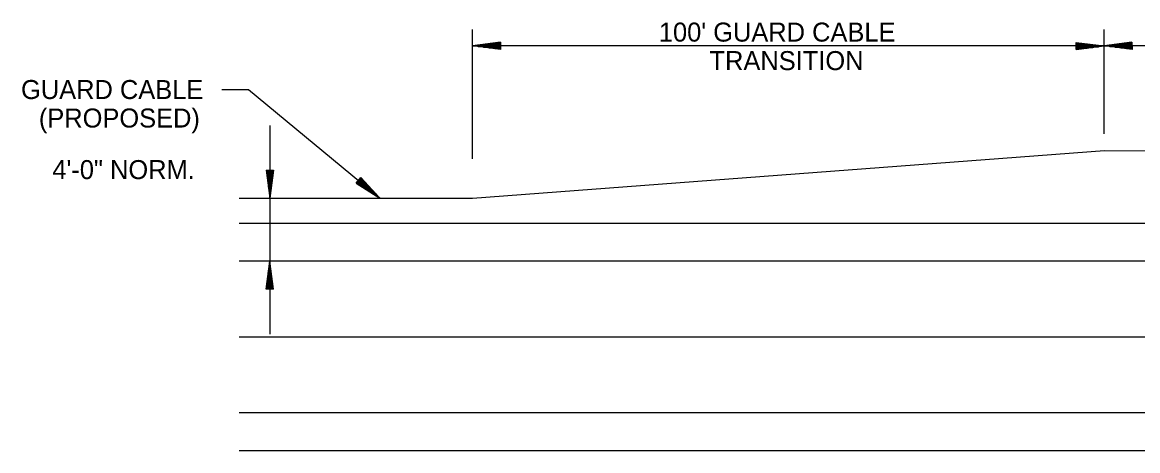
# Model space of a CAD drawing. Extents: x -2842 to 2681, y -2139 to 474.
# Drawn here: x -2842.2 to -2490.2, y -1672.7 to -1537.5 of the extents above; entities that cross this region are included whole.
import ezdxf

# ---------------------------------------------------------------- set-up
doc = ezdxf.new("R2010")
doc.units = 0
for name, color, linetype in [('Default', 7, 'Continuous'), ('R_Border', 7, 'Continuous'), ('R_Border Notes', 7, 'Continuous'), ('R_Grid', 7, 'Continuous')]:
    doc.layers.add(name, color=color, linetype=linetype)

msp = doc.modelspace()

# ---------------------------------------------------------------- linework, layer by layer
at = {"layer": 'Default'}
for p, q in [((-2700.16, -1593), (-2500.66, -1577.94)), ((-2773.74, -1593), (-2700.16, -1593)), ((-2381.26, -1600.97), (-2773.74, -1600.97)), ((-1662.85, -1612.93), (-2773.74, -1612.93)), ((-1661.2, -1660.76), (-2773.74, -1660.76)), ((-1815.02, -1672.72), (-2773.74, -1672.72))]:
    msp.add_line(p, q, dxfattribs=at)
msp.add_lwpolyline([(-2500.66, -1577.94), (-2380.62, -1578.11), (-2266.04, -1580.67)], dxfattribs=at)
at = {"layer": 'R_Border Notes'}
for p, q in [((-2700.16, -1580.53), (-2700.16, -1539.7)), ((-2500.85, -1572.68), (-2500.85, -1539.7)), ((-2691.34, -1543.8), (-2700.16, -1544.95)), ((-2500.85, -1544.95), (-2700.16, -1544.95)), ((-2700.16, -1544.95), (-2691.33, -1544.95)), ((-2691.33, -1546.09), (-2700.16, -1544.95)), ((-2691.34, -1544.72), (-2698.37, -1544.72)), ((-2691.33, -1544.49), (-2696.64, -1544.5)), ((-2691.34, -1544.26), (-2694.86, -1544.26)), ((-2691.33, -1544.03), (-2693.07, -1544.04)), ((-2691.34, -1543.8), (-2691.33, -1546.09)), ((-2509.68, -1544.27), (-2506.15, -1544.26)), ((-2509.68, -1544.49), (-2504.37, -1544.5)), ((-2509.67, -1543.81), (-2500.85, -1544.95)), ((-2509.67, -1546.1), (-2509.67, -1543.81)), ((-2509.67, -1544.03), (-2507.94, -1544.03)), ((-2509.67, -1544.73), (-2502.64, -1544.73)), ((-2500.85, -1544.95), (-2509.67, -1544.95)), ((-2509.67, -1546.1), (-2500.85, -1544.95)), ((-2492.03, -1543.8), (-2500.85, -1544.95)), ((-2363.24, -1544.95), (-2500.85, -1544.95)), ((-2500.85, -1544.95), (-2492.02, -1544.95)), ((-2492.02, -1546.09), (-2500.85, -1544.95)), ((-2492.03, -1544.72), (-2499.06, -1544.72)), ((-2492.02, -1544.49), (-2497.33, -1544.5)), ((-2492.03, -1544.26), (-2495.55, -1544.26)), ((-2492.02, -1544.03), (-2493.76, -1544.04)), ((-2492.03, -1543.8), (-2492.02, -1546.09)), ((-2691.33, -1545.17), (-2698.37, -1545.18)), ((-2691.33, -1545.41), (-2696.63, -1545.41)), ((-2691.33, -1545.63), (-2694.85, -1545.64)), ((-2691.33, -1545.87), (-2693.06, -1545.87)), ((-2509.67, -1545.18), (-2502.64, -1545.18)), ((-2509.67, -1545.41), (-2504.37, -1545.4)), ((-2509.67, -1545.64), (-2506.15, -1545.64)), ((-2509.67, -1545.87), (-2507.94, -1545.86)), ((-2492.02, -1545.17), (-2499.06, -1545.18)), ((-2492.02, -1545.41), (-2497.32, -1545.41)), ((-2492.02, -1545.63), (-2495.54, -1545.64)), ((-2492.02, -1545.87), (-2493.75, -1545.87)), ((-2764.11, -1570.07), (-2764.11, -1593)), ((-2765.26, -1584.18), (-2762.97, -1584.17)), ((-2765.26, -1584.18), (-2764.11, -1593)), ((-2765.03, -1584.17), (-2765.02, -1585.91)), ((-2764.8, -1584.18), (-2764.8, -1587.7)), ((-2764.57, -1584.17), (-2764.56, -1589.48)), ((-2764.34, -1584.18), (-2764.34, -1591.21)), ((-2764.11, -1593), (-2764.11, -1584.17)), ((-2762.97, -1584.17), (-2764.11, -1593)), ((-2763.89, -1584.17), (-2763.88, -1591.21)), ((-2763.65, -1584.17), (-2763.65, -1589.47)), ((-2763.43, -1584.17), (-2763.42, -1587.69)), ((-2763.19, -1584.17), (-2763.19, -1585.9)), ((-2736.86, -1588.25), (-2735.4, -1586.49)), ((-2735.99, -1587.2), (-2730.57, -1591.68)), ((-2735.84, -1587.01), (-2731.76, -1590.4)), ((-2735.7, -1586.84), (-2732.98, -1589.08)), ((-2735.55, -1586.66), (-2734.21, -1587.76)), ((-2735.4, -1586.49), (-2729.34, -1593)), ((-2736.86, -1588.25), (-2729.34, -1593)), ((-2736.72, -1588.08), (-2735.37, -1589.18)), ((-2736.57, -1587.9), (-2733.86, -1590.14)), ((-2736.42, -1587.72), (-2732.33, -1591.1)), ((-2736.27, -1587.55), (-2730.86, -1592.03)), ((-2729.34, -1593), (-2736.13, -1587.37)), ((-2764.11, -1593), (-2764.11, -1612.93)), ((-2765.25, -1621.75), (-2764.11, -1612.93)), ((-2764.33, -1621.75), (-2764.34, -1614.72)), ((-2764.11, -1612.93), (-2764.11, -1635.94)), ((-2764.11, -1612.93), (-2764.11, -1621.75)), ((-2762.96, -1621.75), (-2764.11, -1612.93)), ((-2763.88, -1621.75), (-2763.88, -1614.72)), ((-2764.79, -1621.76), (-2764.8, -1618.23)), ((-2764.57, -1621.76), (-2764.56, -1616.45)), ((-2763.65, -1621.75), (-2763.66, -1616.45)), ((-2763.42, -1621.75), (-2763.42, -1618.23)), ((-2762.96, -1621.75), (-2765.25, -1621.75)), ((-2765.03, -1621.75), (-2765.03, -1620.02)), ((-2763.19, -1621.75), (-2763.2, -1620.02))]:
    msp.add_line(p, q, dxfattribs=at)
msp.add_lwpolyline([(-2779.28, -1558.65), (-2770.79, -1558.65), (-2729.34, -1593)], dxfattribs=at)
at = {"layer": 'R_Grid'}
msp.add_line((-1662.85, -1636.84), (-2773.74, -1636.84), dxfattribs=at)

# ---------------------------------------------------------------- texts
at = {"layer": 'R_Border'}
for s, p in [("100' GUARD CABLE", (-2641.32, -1543.57)), ('TRANSITION', (-2625.33, -1552.57)), ('4\'-0" NORM.', (-2832.71, -1586.98))]:
    msp.add_text(s, height=6, dxfattribs=at).set_placement(p)
for s, p in [('GUARD CABLE', (-2842.59, -1561.7)), ('(PROPOSED)', (-2836.97, -1570.7))]:
    msp.add_text(s, height=6, rotation=359.9999, dxfattribs=at).set_placement(p)

doc.saveas('drawing.dxf')
